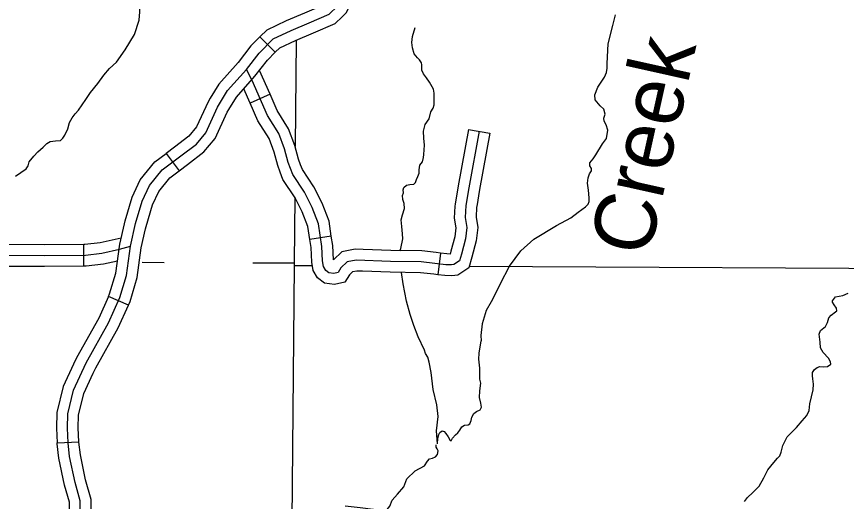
# Model space of a CAD drawing. Extents: x 813775 to 1157140, y 1757555 to 1979907.
# Drawn here: x 919670 to 931113, y 1830487 to 1837175 of the extents above; entities that cross this region are included whole.
import ezdxf

# ---------------------------------------------------------------- set-up
doc = ezdxf.new("R2010")
doc.units = 0
for name, color, linetype in [('Level 31', 7, 'Continuous'), ('Level 32', 7, 'Continuous'), ('Level 35', 7, 'Continuous'), ('Level 4', 7, 'Continuous'), ('Level 45', 7, 'Continuous'), ('Level 5', 7, 'Continuous')]:
    doc.layers.add(name, color=color, linetype=linetype)

msp = doc.modelspace()

# ---------------------------------------------------------------- linework, layer by layer
at = {"layer": 'Level 31'}
for p, q in [((923237, 1836683), (923025, 1836895)), ((923025, 1836895), (923025, 1836895)), ((921732, 1835288), (921911, 1835047)), ((921211, 1833194), (920937, 1833315)), ((920229, 1831294), (920528, 1831307)), ((920528, 1831307), (920528, 1831307))]:
    msp.add_line(p, q, dxfattribs=at)
for points in [[(924158, 1837170), (924219, 1837229), (924313, 1837440), (924337, 1837810), (924350, 1838055), (924398, 1838259), (924400, 1838283)], [(923025, 1836895), (923123, 1836992), (923393, 1837120), (923645, 1837228), (923895, 1837333), (923950, 1837386)], [(923237, 1836683), (923298, 1836743), (923516, 1836847), (923762, 1836952), (924062, 1837078), (924158, 1837170)], [(923025, 1836895), (922902, 1836772), (922726, 1836543), (922459, 1836244), (922340, 1836049)], [(922597, 1835893), (922701, 1836065), (922957, 1836352), (923128, 1836573), (923237, 1836683)], [(923890, 1833804), (923881, 1834004), (923832, 1834315), (923747, 1834542), (923641, 1834751), (923477, 1834995), (923415, 1835164), (923366, 1835351), (923286, 1835560), (923130, 1835808), (922917, 1836293), (922842, 1836447)], [(922340, 1836049), (922310, 1835998), (922150, 1835653), (922044, 1835525), (921846, 1835372), (921732, 1835288)], [(921911, 1835047), (922027, 1835132), (922254, 1835308), (922406, 1835491), (922575, 1835857), (922597, 1835893)], [(926047, 1835592), (925905, 1834814), (925865, 1834570), (925856, 1834401), (925879, 1834263), (925861, 1834108), (925803, 1833899), (925777, 1833805), (925698, 1833753)], [(921156, 1834315), (921165, 1834357), (921263, 1834683), (921373, 1834923), (921574, 1835170), (921732, 1835288)], [(921448, 1834249), (921455, 1834281), (921544, 1834577), (921629, 1834763), (921783, 1834952), (921911, 1835047)], [(920937, 1833315), (920953, 1833351), (921040, 1833637), (921092, 1834036), (921156, 1834315)], [(921211, 1833194), (921234, 1833246), (921334, 1833574), (921388, 1833983), (921448, 1834249)], [(918142, 1833916), (918210, 1833916), (919402, 1833885), (920055, 1833881), (920618, 1833885), (920845, 1833912), (921089, 1833965), (921240, 1834010)], [(925698, 1833753), (925666, 1833748), (925590, 1833752), (925439, 1833770), (925248, 1833792), (924826, 1833797), (924351, 1833814), (924227, 1833792), (924143, 1833708), (924103, 1833645), (924045, 1833632), (923974, 1833641), (923934, 1833672), (923903, 1833725), (923890, 1833804)], [(920937, 1833315), (920804, 1833015), (920494, 1832465), (920454, 1832380)], [(920726, 1832254), (920761, 1832328), (921072, 1832880), (921211, 1833194)], [(920454, 1832380), (920312, 1832073), (920225, 1831714), (920220, 1831496), (920229, 1831294)], [(920528, 1831307), (920520, 1831500), (920524, 1831675), (920596, 1831974), (920726, 1832254)], [(920393, 1830289), (920397, 1830474), (920331, 1830711), (920253, 1831083), (920229, 1831281), (920229, 1831294)], [(920688, 1830232), (920693, 1830253), (920698, 1830513), (920622, 1830783), (920549, 1831131), (920528, 1831306), (920528, 1831307)]]:
    msp.add_lwpolyline(points, dxfattribs=at)
at = {"layer": 'Level 32'}
msp.add_line((920598, 1833735), (920596, 1834035), dxfattribs=at)
for points in [[(921240, 1834010), (921310, 1834319), (921403, 1834630), (921501, 1834843), (921679, 1835061), (921936, 1835252), (922149, 1835416), (922278, 1835572), (922442, 1835927), (922580, 1836154), (922842, 1836447), (923015, 1836672), (923210, 1836868), (923455, 1836983), (923703, 1837090), (923978, 1837206), (924094, 1837317), (924165, 1837477), (924187, 1837819), (924200, 1838077)], [(920596, 1834035), (920609, 1834035), (920820, 1834060), (921112, 1834123)], [(919542, 1834034), (920054, 1834031), (920596, 1834035)], [(919797, 1827190), (919806, 1827381), (919864, 1827688), (920019, 1828323), (920281, 1829305), (920490, 1830031), (920543, 1830271), (920547, 1830494), (920476, 1830747), (920401, 1831107), (920379, 1831294), (920370, 1831498), (920374, 1831694), (920454, 1832023), (920627, 1832397), (920938, 1832948), (921093, 1833299), (921187, 1833605), (921240, 1834010)], [(919540, 1833734), (920055, 1833731), (920598, 1833735)], [(920598, 1833735), (920628, 1833735), (920870, 1833764), (921062, 1833805)]]:
    msp.add_lwpolyline(points, dxfattribs=at)
at = {"layer": 'Level 35'}
for points in [[(920789, 1836253), (920871, 1836365), (920949, 1836458), (921049, 1836544), (921168, 1836715), (921295, 1836927), (921360, 1837126), (921370, 1837240), (921373, 1837326)], [(927812, 1836528), (927829, 1836800), (927890, 1837050), (927931, 1837199)], [(925429, 1835999), (925427, 1836117), (925419, 1836175), (925363, 1836271), (925321, 1836332), (925282, 1836386), (925260, 1836435), (925258, 1836508), (925253, 1836538), (925224, 1836577), (925199, 1836604), (925153, 1836660), (925128, 1836743), (925121, 1836819), (925128, 1836900), (925165, 1837022)], [(927658, 1835266), (927748, 1835421), (927807, 1835492), (927821, 1835610), (927802, 1835681), (927772, 1835732), (927767, 1835774), (927787, 1835830), (927767, 1835896), (927716, 1835945), (927648, 1836026), (927643, 1836094), (927687, 1836202), (927777, 1836337), (927807, 1836405), (927814, 1836464), (927812, 1836528)], [(919656, 1834973), (919803, 1835075), (919827, 1835116), (919845, 1835171), (919907, 1835248), (919961, 1835308), (920036, 1835375), (920085, 1835422), (920132, 1835453), (920204, 1835463), (920274, 1835466), (920308, 1835497), (920336, 1835541), (920377, 1835624), (920401, 1835712), (920434, 1835779), (920476, 1835831), (920525, 1835883), (920626, 1836033), (920688, 1836126), (920789, 1836253)], [(925287, 1835271), (925295, 1835401), (925285, 1835497), (925282, 1835592), (925302, 1835688), (925358, 1835766), (925383, 1835859), (925414, 1835913), (925427, 1835959), (925429, 1835999)], [(924957, 1833945), (924969, 1833974), (924998, 1834109), (924993, 1834177), (924981, 1834278), (924971, 1834373), (924993, 1834439), (925020, 1834527), (925015, 1834596), (924998, 1834652), (924993, 1834708), (925003, 1834745), (925001, 1834784), (925011, 1834816), (925047, 1834848), (925094, 1834858), (925147, 1834865), (925172, 1834885), (925184, 1834926), (925204, 1834970), (925223, 1835014), (925221, 1835061), (925231, 1835124), (925267, 1835173), (925282, 1835230), (925287, 1835271)], [(926343, 1833492), (926465, 1833732), (926624, 1833945), (926802, 1834102), (927113, 1834292), (927311, 1834400), (927416, 1834478), (927514, 1834552), (927550, 1834589), (927565, 1834623), (927565, 1834674), (927555, 1834782), (927545, 1834877), (927553, 1834951), (927572, 1835007), (927599, 1835049), (927599, 1835078), (927577, 1835115), (927577, 1835156), (927621, 1835213), (927658, 1835266)], [(925473, 1831281), (925460, 1831462), (925482, 1831658), (925463, 1831817), (925414, 1832030), (925385, 1832265), (925360, 1832409), (925343, 1832478), (925309, 1832527), (925294, 1832571), (925209, 1832755), (925150, 1832914), (925096, 1833066), (925047, 1833249), (925001, 1833487), (924978, 1833645)], [(926343, 1833492), (926216, 1833241), (926145, 1833119), (926089, 1832935), (926070, 1832776), (926076, 1832703)], [(930791, 1832541), (930755, 1832605), (930750, 1832684), (930739, 1832792), (930755, 1832844), (930826, 1832899), (930853, 1832953), (930872, 1833021), (930902, 1833056), (930965, 1833103), (930981, 1833116), (930978, 1833154), (930943, 1833198), (930921, 1833236), (930921, 1833255), (930962, 1833309), (931062, 1833328), (931136, 1833361)], [(925473, 1831281), (925481, 1831360), (925494, 1831408), (925507, 1831436), (925537, 1831461), (925567, 1831449), (925590, 1831423), (925620, 1831378), (925645, 1831335), (925663, 1831322), (925681, 1831360), (925721, 1831403), (925754, 1831431), (925784, 1831471), (925809, 1831514), (925847, 1831539), (925895, 1831542), (925920, 1831557), (925938, 1831602), (925948, 1831648), (925973, 1831701), (926011, 1831729), (926061, 1831751), (926081, 1831789), (926074, 1831842), (926054, 1831918), (926059, 1832014), (926071, 1832120), (926056, 1832175), (926059, 1832226), (926056, 1832327), (926044, 1832448), (926051, 1832531), (926076, 1832703)], [(930297, 1831379), (930424, 1831505), (930503, 1831600), (930568, 1831674), (930598, 1831742), (930609, 1831834), (930653, 1832027), (930661, 1832106), (930650, 1832177), (930647, 1832218), (930644, 1832264), (930672, 1832307), (930712, 1832332), (930745, 1832346), (930797, 1832343), (930854, 1832348), (930900, 1832378), (930892, 1832414), (930867, 1832462), (930791, 1832541)], [(929707, 1830484), (929748, 1830541), (929821, 1830611), (929908, 1830698), (929976, 1830810), (930028, 1830922), (930112, 1831025), (930161, 1831082), (930196, 1831115), (930215, 1831164), (930237, 1831259), (930267, 1831321), (930297, 1831379)], [(924200, 1830427), (924408, 1830401), (924585, 1830381), (924675, 1830358), (924721, 1830363), (924781, 1830376), (924817, 1830421), (924849, 1830502), (924922, 1830588), (925011, 1830686), (925053, 1830797), (925167, 1830908), (925293, 1830976), (925338, 1831042), (925366, 1831072), (925404, 1831085), (925447, 1831100), (925474, 1831135), (925484, 1831186), (925469, 1831213), (925457, 1831236), (925457, 1831266)]]:
    msp.add_lwpolyline(points, dxfattribs=at)
at = {"layer": 'Level 4'}
for points in [[(923527, 1836851), (923513, 1835382)], [(923506, 1834683), (923497, 1833778), (923497, 1833742), (923452, 1828706)]]:
    msp.add_lwpolyline(points, dxfattribs=at)
at = {"layer": 'Level 45'}
for p, q in [((923165, 1836103), (922890, 1835982)), ((925900, 1835619), (926195, 1835565)), ((924010, 1834145), (923714, 1834099)), ((925517, 1833912), (925481, 1833614))]:
    msp.add_line(p, q, dxfattribs=at)
for points in [[(923165, 1836103), (923020, 1836433)], [(922890, 1835982), (922803, 1836179)], [(923586, 1835131), (923558, 1835209), (923509, 1835397), (923421, 1835627), (923263, 1835879), (923165, 1836103)], [(923305, 1835028), (923271, 1835119), (923223, 1835305), (923151, 1835492), (922997, 1835738), (922890, 1835982)], [(925900, 1835619), (925757, 1834840), (925716, 1834586), (925715, 1834560)], [(926195, 1835565), (926053, 1834789), (926015, 1834554), (926014, 1834544)], [(924010, 1834145), (923978, 1834353), (923885, 1834602), (923770, 1834827), (923611, 1835064), (923586, 1835131)], [(923714, 1834099), (923686, 1834277), (923610, 1834481), (923511, 1834674), (923342, 1834926), (923305, 1835028)], [(926014, 1834544), (926007, 1834409), (926030, 1834267), (926009, 1834079), (925948, 1833858), (925906, 1833711), (925754, 1833609), (925673, 1833597), (925577, 1833603), (925481, 1833614)], [(925715, 1834560), (925706, 1834393), (925727, 1834260), (925713, 1834136), (925659, 1833939), (925647, 1833899), (925647, 1833899), (925603, 1833902), (925517, 1833912)], [(924439, 1833661), (924362, 1833664), (924300, 1833653), (924260, 1833613), (924196, 1833513), (924053, 1833480), (923914, 1833497), (923819, 1833572), (923760, 1833673), (923740, 1833788), (923731, 1833989), (923714, 1834099)], [(924451, 1833961), (924341, 1833965), (924154, 1833931), (924040, 1833817), (924039, 1833820), (924030, 1834019), (924010, 1834145)], [(925517, 1833912), (925457, 1833919), (925258, 1833942), (924830, 1833946), (924451, 1833961)], [(925481, 1833614), (925422, 1833621), (925239, 1833642), (924823, 1833647), (924439, 1833661)]]:
    msp.add_lwpolyline(points, dxfattribs=at)
at = {"layer": 'Level 5'}
for points in [[(921401, 1833785), (921707, 1833784)], [(922928, 1833780), (923497, 1833778)], [(923497, 1833742), (923748, 1833741)], [(925911, 1833730), (932894, 1833694)]]:
    msp.add_lwpolyline(points, dxfattribs=at)

# ---------------------------------------------------------------- texts
at = {"layer": 'Level 35'}
msp.add_text('Creek', height=844.8, rotation=77.4236, dxfattribs=at).set_placement((928390, 1833838))

doc.saveas('drawing.dxf')
